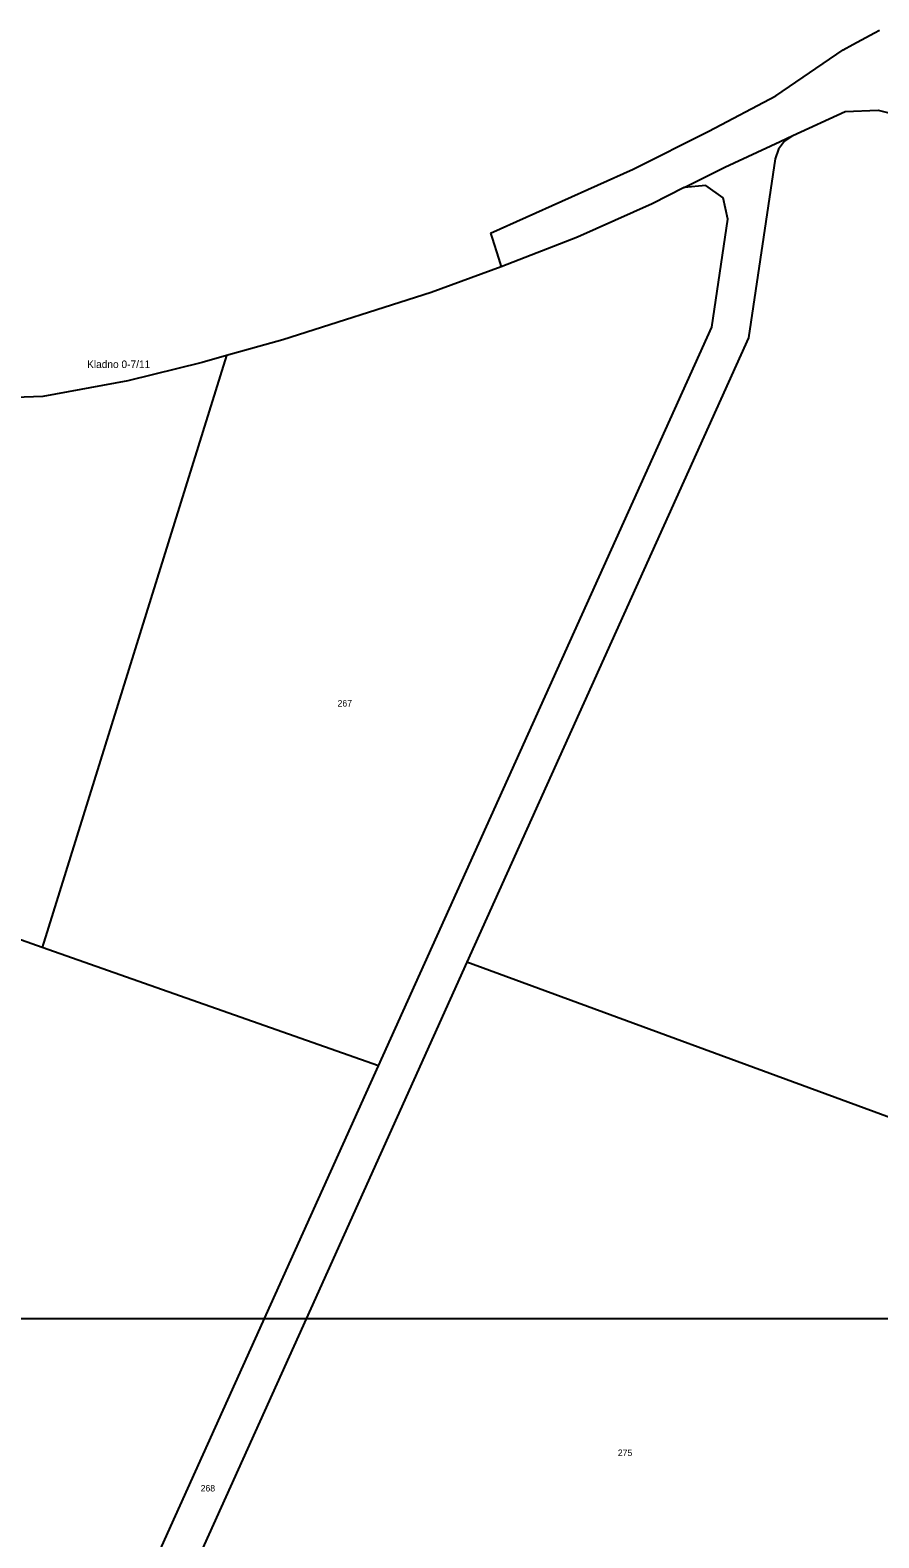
# Model space of a CAD drawing. Extents: x -752500 to -750336, y -1035826 to -1033500.
# Drawn here: x -752217.4 to -751993.6, y -1034557.7 to -1034160.4 of the extents above; entities that cross this region are included whole.
import ezdxf

# ---------------------------------------------------------------- set-up
doc = ezdxf.new("R2010")
doc.units = 0
for name, color, linetype in [('Hranice kat_území', 7, 'Continuous'), ('Hranice parcel', 7, 'Continuous'), ('ML1000', 7, 'Continuous'), ('Parcelní čísla', 7, 'Continuous')]:
    doc.layers.add(name, color=color, linetype=linetype)

msp = doc.modelspace()

# ---------------------------------------------------------------- linework, layer by layer
at = {"layer": 'Hranice kat_území'}
for p, q in [((-752000.53, -1034164.18), (-751994.78, -1034161.06)), ((-751994.78, -1034161.06), (-751993.48, -1034160.36)), ((-752020.78, -1034177.67), (-752003.02, -1034165.53)), ((-752003.02, -1034165.53), (-752000.53, -1034164.18)), ((-752038.45, -1034186.99), (-752020.78, -1034177.67)), ((-752058.44, -1034196.97), (-752038.45, -1034186.99)), ((-752096.03, -1034213.82), (-752058.44, -1034196.97)), ((-752096.03, -1034213.82), (-752095.59, -1034215.22)), ((-752095.59, -1034215.22), (-752093.93, -1034220.45)), ((-752093.21, -1034222.73), (-752111.65, -1034229.51)), ((-752093.93, -1034220.45), (-752093.21, -1034222.73)), ((-752111.65, -1034229.51), (-752150.84, -1034241.93)), ((-752150.84, -1034241.93), (-752165.63, -1034246.11)), ((-752165.63, -1034246.11), (-752172.08, -1034247.92)), ((-752172.08, -1034247.92), (-752191.65, -1034252.76)), ((-752191.65, -1034252.76), (-752214.1, -1034256.88)), ((-752214.1, -1034256.88), (-752234.9, -1034257.62)), ((-752214.25, -1034402.11), (-752273.45, -1034381.33)), ((-752125.54, -1034433.28), (-752214.25, -1034402.11)), ((-752181.09, -1034556.37), (-752125.54, -1034433.28)), ((-752214.83, -1034631.16), (-752181.09, -1034556.37))]:
    msp.add_line(p, q, dxfattribs=at)
at = {"layer": 'Hranice parcel'}
for p, q in [((-752016.35, -1034188.16), (-752002.51, -1034181.84)), ((-752002.51, -1034181.84), (-751993.79, -1034181.43)), ((-751993.79, -1034181.43), (-751981.52, -1034184.46)), ((-752034.29, -1034196.46), (-752019.65, -1034189.68)), ((-752018.52, -1034189.62), (-752020.14, -1034191.76)), ((-752019.65, -1034189.68), (-752016.35, -1034188.16)), ((-752016.35, -1034188.16), (-752018.52, -1034189.62)), ((-752020.94, -1034194.25), (-752028.02, -1034241.47)), ((-752020.14, -1034191.76), (-752020.94, -1034194.25)), ((-752044.96, -1034201.86), (-752034.29, -1034196.46)), ((-752044.96, -1034201.86), (-752053.38, -1034206.12)), ((-752039.26, -1034201.28), (-752044.96, -1034201.86)), ((-752034.68, -1034204.58), (-752039.26, -1034201.28)), ((-752053.38, -1034206.12), (-752073.06, -1034214.95)), ((-752033.44, -1034210.19), (-752034.68, -1034204.58)), ((-752037.7, -1034238.62), (-752033.44, -1034210.19)), ((-752073.06, -1034214.95), (-752093.21, -1034222.73)), ((-752081.62, -1034335.95), (-752037.7, -1034238.62)), ((-752028.02, -1034241.47), (-752102.26, -1034405.99)), ((-752165.63, -1034246.11), (-752214.25, -1034402.11)), ((-752125.54, -1034433.28), (-752081.62, -1034335.95)), ((-752102.26, -1034405.99), (-752143.42, -1034497.22)), ((-751947.46, -1034462.91), (-752102.26, -1034405.99)), ((-752143.42, -1034497.22), (-752184.59, -1034588.46))]:
    msp.add_line(p, q, dxfattribs=at)
at = {"layer": 'ML1000'}
msp.add_lwpolyline([(-751250, -1034500), (-751875, -1034500), (-752500, -1034500)], dxfattribs=at)

# ---------------------------------------------------------------- texts
msp.add_text('Kladno 0-7/11', height=2, dxfattribs=at).set_placement((-752202.42, -1034249.41))
at = {"layer": 'Parcelní čísla'}
for s, p in [('267', (-752136.36, -1034338.62)), ('275', (-752062.46, -1034536.12)), ('268', (-752172.46, -1034545.47))]:
    msp.add_text(s, height=1.7, dxfattribs=at).set_placement(p)

doc.saveas('drawing.dxf')
